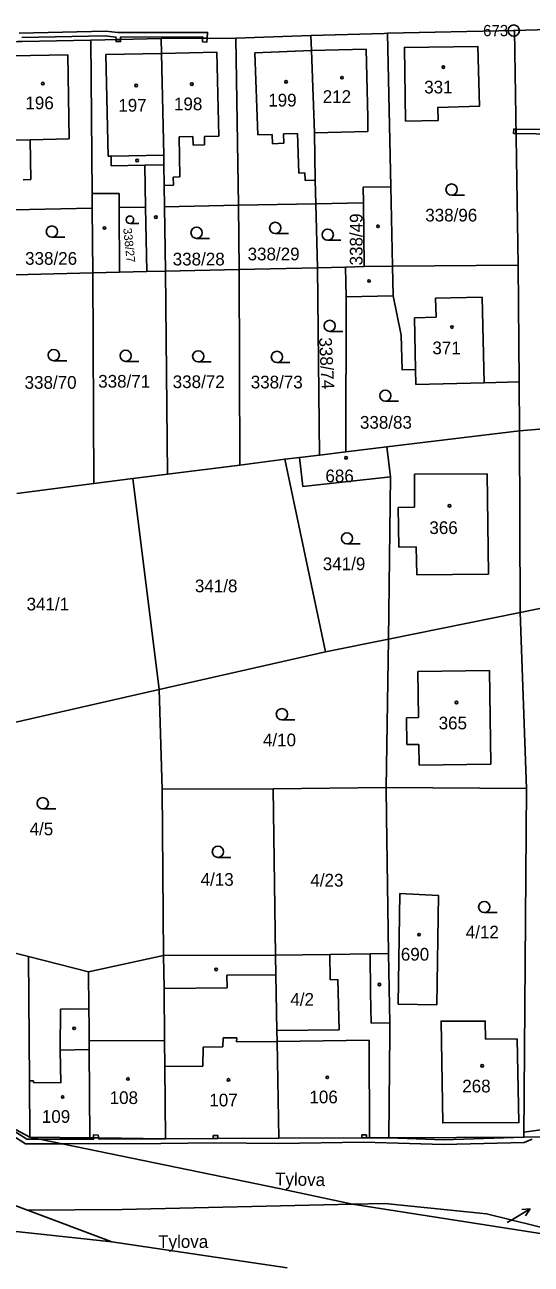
# Model space of a CAD drawing. Extents: x -758582 to -751794, y -998770 to -994350.
# Drawn here: x -755831.8 to -755764, y -995507.3 to -995341.4 of the extents above; entities that cross this region are included whole.
import ezdxf

# ---------------------------------------------------------------- set-up
doc = ezdxf.new("R2010")
doc.units = 0
for name, color, linetype in [('Hranice parcel', 7, 'Continuous'), ('Parcelní čísla', 7, 'Continuous'), ('Pop  PČ popisy', 7, 'Continuous'), ('Vnitřní kresba', 7, 'Continuous'), ('Věcná břemena k části', 7, 'Continuous'), ('Značky bodu BP', 7, 'Continuous'), ('Značky budov', 7, 'Continuous'), ('Značky kultur', 7, 'Continuous')]:
    doc.layers.add(name, color=color, linetype=linetype)

msp = doc.modelspace()

# ---------------------------------------------------------------- linework, layer by layer
at = {"layer": 'Hranice parcel'}
for p, q in [((-755766.27, -995342.19), (-755783.26, -995342.59)), ((-755753.88, -995341.9), (-755766.27, -995342.19)), ((-755765.77, -995373.61), (-755766.27, -995342.19)), ((-755813.51, -995343.29), (-755822.92, -995343.49)), ((-755803.52, -995343.22), (-755813.51, -995343.29)), ((-755793.5, -995342.86), (-755803.52, -995343.22)), ((-755803.19, -995365.6), (-755803.52, -995343.22)), ((-755803.19, -995365.6), (-755792.83, -995365.4)), ((-755792.61, -995373.94), (-755792.83, -995365.4)), ((-755833.22, -995366.18), (-755822.74, -995365.98)), ((-755822.74, -995365.98), (-755822.67, -995374.63)), ((-755813.08, -995365.79), (-755803.19, -995365.6)), ((-755812.97, -995374.41), (-755813.08, -995365.79)), ((-755803.07, -995374.18), (-755803.19, -995365.6)), ((-755786.36, -995373.8), (-755782.59, -995373.72)), ((-755765.77, -995373.61), (-755782.59, -995373.72)), ((-755765.64, -995389.23), (-755765.77, -995373.61)), ((-755833.1, -995374.88), (-755822.67, -995374.63)), ((-755822.67, -995374.63), (-755819.1, -995374.55)), ((-755822.55, -995402.8), (-755822.67, -995374.63)), ((-755819.1, -995374.55), (-755815.43, -995374.47)), ((-755815.43, -995374.47), (-755812.97, -995374.41)), ((-755812.97, -995374.41), (-755803.07, -995374.18)), ((-755812.7, -995401.57), (-755812.97, -995374.41)), ((-755803.07, -995374.18), (-755792.61, -995373.94)), ((-755802.99, -995400.37), (-755803.07, -995374.18)), ((-755792.61, -995373.94), (-755788.87, -995373.86)), ((-755792.34, -995399), (-755792.61, -995373.94)), ((-755786.36, -995373.8), (-755788.87, -995373.86)), ((-755788.87, -995373.86), (-755788.78, -995377.86)), ((-755788.82, -995398.58), (-755788.78, -995377.86)), ((-755765.58, -995395.77), (-755765.64, -995389.23)), ((-755765.58, -995395.77), (-755753.54, -995394.8)), ((-755765.58, -995395.77), (-755783.34, -995397.92)), ((-755765.49, -995420.07), (-755765.58, -995395.77)), ((-755792.34, -995399), (-755788.82, -995398.58)), ((-755788.82, -995398.58), (-755783.34, -995397.92)), ((-755783.34, -995397.92), (-755782.83, -995401.91)), ((-755802.99, -995400.37), (-755796.97, -995399.56)), ((-755796.97, -995399.56), (-755795.01, -995399.32)), ((-755791.55, -995425.33), (-755796.97, -995399.56)), ((-755795.01, -995399.32), (-755792.34, -995399)), ((-755817.31, -995402.15), (-755812.7, -995401.57)), ((-755812.7, -995401.57), (-755802.99, -995400.37)), ((-755782.83, -995401.91), (-755783.13, -995423.63)), ((-755832.84, -995404.14), (-755822.55, -995402.8)), ((-755822.55, -995402.8), (-755817.31, -995402.15)), ((-755813.81, -995430.38), (-755817.31, -995402.15)), ((-755753, -995417.54), (-755765.49, -995420.07)), ((-755765.49, -995420.07), (-755783.13, -995423.63)), ((-755764.66, -995443.61), (-755765.49, -995420.07)), ((-755783.13, -995423.63), (-755791.55, -995425.33)), ((-755783.13, -995423.63), (-755783.4, -995443.47)), ((-755791.55, -995425.33), (-755813.81, -995430.38)), ((-755813.81, -995430.38), (-755838.55, -995435.99)), ((-755813.4, -995443.71), (-755813.81, -995430.38)), ((-755813.4, -995443.71), (-755798.53, -995443.67)), ((-755813.22, -995465.96), (-755813.4, -995443.71)), ((-755798.53, -995443.67), (-755783.4, -995443.47)), ((-755798.21, -995465.91), (-755798.53, -995443.67)), ((-755783.4, -995443.47), (-755764.66, -995443.61)), ((-755764.66, -995443.61), (-755764.98, -995490.26)), ((-755831.29, -995466.07), (-755840.09, -995463.93)), ((-755823.23, -995468.14), (-755831.29, -995466.07)), ((-755813.22, -995465.96), (-755823.23, -995468.14)), ((-755798.21, -995465.91), (-755813.22, -995465.96)), ((-755790.97, -995465.81), (-755798.21, -995465.91)), ((-755840.32, -995485.32), (-755831.1, -995490.25)), ((-755831.1, -995490.25), (-755823.09, -995490.34)), ((-755783.06, -995490.34), (-755764.98, -995490.26)), ((-755764.98, -995490.26), (-755751.84, -995489.99)), ((-755787.94, -995499.24), (-755783.62, -995499.14)), ((-755787.94, -995499.24), (-755753.53, -995504.57)), ((-755783.62, -995499.14), (-755769.99, -995500.51)), ((-755820.13, -995504.28), (-755831.43, -995500.02)), ((-755769.99, -995500.51), (-755753.53, -995504.57)), ((-755796.67, -995507.74), (-755820.13, -995504.28))]:
    msp.add_line(p, q, dxfattribs=at)
for points in [[(-755822.92, -995343.49), (-755832.14, -995343.69), (-755832.74, -995343.7), (-755833.54, -995343.72)], [(-755822.74, -995365.98), (-755822.76, -995364.02), (-755822.92, -995343.49)], [(-755813.08, -995365.79), (-755813.11, -995362.95), (-755813.16, -995360.19), (-755813.19, -995358.89), (-755813.47, -995345.29), (-755813.51, -995343.29)], [(-755783.26, -995342.59), (-755783.7, -995342.63), (-755793.5, -995342.86)], [(-755792.83, -995365.4), (-755792.9, -995362.24), (-755793.03, -995355.91), (-755793.43, -995344.9), (-755793.5, -995342.86)], [(-755782.59, -995373.72), (-755782.77, -995365.18), (-755782.81, -995363.13), (-755783.26, -995342.59)], [(-755780.84, -995354.32), (-755776.47, -995354.26), (-755776.52, -995352.5), (-755770.92, -995352.33), (-755771.16, -995344.33), (-755780.99, -995344.47), (-755780.84, -995354.32)], [(-755792.83, -995365.4), (-755786.47, -995365.26), (-755786.36, -995373.8)], [(-755819.1, -995374.55), (-755819.14, -995365.91), (-755815.61, -995365.84), (-755815.43, -995374.47)], [(-755788.78, -995377.86), (-755782.5, -995377.72), (-755781.4, -995382.99), (-755781.29, -995387.59), (-755779.49, -995387.55), (-755779.45, -995389.55), (-755770.32, -995389.34), (-755765.64, -995389.23)], [(-755782.83, -995401.91), (-755794.56, -995403.23), (-755795.01, -995399.32)], [(-755783.4, -995443.47), (-755783.37, -995447.37), (-755783.09, -995465.69)], [(-755781.83, -995472.46), (-755781.59, -995457.66), (-755776.41, -995457.93), (-755776.65, -995472.54), (-755781.83, -995472.46)], [(-755831.29, -995466.07), (-755831.16, -995482.73), (-755831.1, -995490.25)], [(-755813.22, -995465.96), (-755813.12, -995470.35), (-755813.07, -995477.31), (-755813.02, -995480.79), (-755812.97, -995490.5)], [(-755798.04, -995475.98), (-755798.17, -995468.52), (-755798.21, -995465.91)], [(-755790.97, -995465.81), (-755790.91, -995469.19), (-755789.89, -995469.16), (-755789.73, -995475.88), (-755798.04, -995475.98)], [(-755783.09, -995465.69), (-755785.58, -995465.73), (-755790.97, -995465.81)], [(-755783.06, -995490.34), (-755782.93, -995476.29), (-755782.95, -995474.96), (-755783.09, -995465.69)], [(-755823.23, -995468.14), (-755823.19, -995473.14), (-755823.18, -995475.27), (-755823.17, -995477.38), (-755823.16, -995478.54), (-755823.09, -995490.34)], [(-755831.43, -995500.02), (-755834.39, -995498.91), (-755843.49, -995495.24), (-755854.92, -995487.79), (-755869.22, -995474.51)], [(-755765.89, -995477.1), (-755770.13, -995477.13), (-755770.16, -995474.73), (-755776.08, -995474.73), (-755775.85, -995488.36), (-755765.66, -995488.3), (-755765.89, -995477.1)], [(-755798.04, -995475.98), (-755798.01, -995477.44), (-755797.79, -995490.38)], [(-755831.1, -995490.25), (-755797.72, -995497.11), (-755787.94, -995499.24)], [(-755823.09, -995490.34), (-755822.57, -995490.35), (-755821.87, -995490.36), (-755812.97, -995490.5)], [(-755812.97, -995490.5), (-755806.55, -995490.45), (-755805.95, -995490.44), (-755797.79, -995490.38)], [(-755797.79, -995490.38), (-755785.65, -995490.33), (-755783.06, -995490.34)], [(-755831.43, -995500.02), (-755818.76, -995499.95), (-755787.94, -995499.24)], [(-755862.96, -995509.12), (-755847.86, -995501.28), (-755820.13, -995504.28)]]:
    msp.add_lwpolyline(points, dxfattribs=at)
at = {"layer": 'Pop  PČ popisy'}
for p, q in [((-755767.21, -995501.68), (-755766.74, -995501.4)), ((-755766.74, -995501.4), (-755764.17, -995499.85)), ((-755764.17, -995499.85), (-755765.28, -995499.94)), ((-755764.17, -995499.85), (-755764.77, -995500.8))]:
    msp.add_line(p, q, dxfattribs=at)
at = {"layer": 'Vnitřní kresba'}
for p, q in [((-755826.03, -995345.47), (-755833.49, -995345.61)), ((-755825.82, -995356.72), (-755826.03, -995345.47)), ((-755820.92, -995345.44), (-755813.47, -995345.29)), ((-755820.64, -995359.04), (-755820.92, -995345.44)), ((-755806.07, -995345.13), (-755813.47, -995345.29)), ((-755805.83, -995356.33), (-755806.07, -995345.13)), ((-755793.43, -995344.9), (-755800.99, -995345.18)), ((-755800.99, -995345.18), (-755800.59, -995356.18)), ((-755793.43, -995344.9), (-755786.08, -995344.73)), ((-755786.08, -995344.73), (-755785.89, -995353.84)), ((-755785.89, -995353.84), (-755785.86, -995355.73)), ((-755833.35, -995356.89), (-755831.07, -995356.84)), ((-755831.07, -995356.84), (-755825.82, -995356.72)), ((-755830.96, -995362.15), (-755831.07, -995356.84)), ((-755811.13, -995356.44), (-755809.28, -995356.4)), ((-755811.02, -995361.79), (-755811.13, -995356.44)), ((-755809.28, -995356.4), (-755809.26, -995357.55)), ((-755807.73, -995356.37), (-755805.83, -995356.33)), ((-755807.71, -995357.52), (-755807.73, -995356.37)), ((-755798.69, -995356.11), (-755800.59, -995356.18)), ((-755798.65, -995357.36), (-755798.69, -995356.11)), ((-755795.29, -995355.99), (-755797.14, -995356.05)), ((-755797.14, -995356.05), (-755797.1, -995357.3)), ((-755795.1, -995361.28), (-755795.29, -995355.99)), ((-755785.86, -995355.73), (-755793.03, -995355.91)), ((-755809.26, -995357.55), (-755807.71, -995357.52)), ((-755797.1, -995357.3), (-755798.65, -995357.36)), ((-755820.24, -995359.03), (-755820.64, -995359.04)), ((-755813.19, -995358.89), (-755820.24, -995359.03)), ((-755820.22, -995360.33), (-755820.24, -995359.03)), ((-755815.72, -995360.24), (-755820.22, -995360.33)), ((-755813.16, -995360.19), (-755815.72, -995360.24)), ((-755815.61, -995365.84), (-755815.72, -995360.24)), ((-755831.98, -995362.17), (-755830.96, -995362.15)), ((-755811.9, -995361.81), (-755811.02, -995361.79)), ((-755811.87, -995362.92), (-755811.9, -995361.81)), ((-755794.32, -995361.26), (-755795.1, -995361.28)), ((-755794.28, -995362.29), (-755794.32, -995361.26)), ((-755813.11, -995362.95), (-755811.87, -995362.92)), ((-755792.9, -995362.24), (-755794.28, -995362.29)), ((-755786.5, -995363.18), (-755782.81, -995363.13)), ((-755786.47, -995365.26), (-755786.5, -995363.18)), ((-755822.76, -995364.02), (-755819.15, -995364)), ((-755819.15, -995364), (-755819.14, -995365.91)), ((-755782.5, -995377.72), (-755782.59, -995373.72)), ((-755776.81, -995378.01), (-755770.58, -995377.87)), ((-755776.81, -995378.01), (-755776.75, -995380.58)), ((-755770.58, -995377.87), (-755770.32, -995389.34)), ((-755776.75, -995380.58), (-755779.65, -995380.65)), ((-755779.65, -995380.65), (-755779.49, -995387.55)), ((-755769.92, -995401.53), (-755779.65, -995401.57)), ((-755779.63, -995406), (-755779.65, -995401.57)), ((-755769.92, -995401.53), (-755769.74, -995414.92)), ((-755779.63, -995406), (-755781.8, -995406.03)), ((-755781.8, -995406.03), (-755781.73, -995411.33)), ((-755781.73, -995411.33), (-755779.39, -995411.3)), ((-755779.39, -995411.3), (-755779.34, -995415.05)), ((-755779.34, -995415.05), (-755769.74, -995414.92)), ((-755779.17, -995427.97), (-755769.58, -995427.84)), ((-755779.1, -995434.12), (-755779.17, -995427.97)), ((-755769.58, -995427.84), (-755769.41, -995440.38)), ((-755779.1, -995434.12), (-755780.71, -995434.15)), ((-755780.71, -995434.15), (-755780.66, -995437.73)), ((-755780.66, -995437.73), (-755779.04, -995437.71)), ((-755779.04, -995437.71), (-755779, -995440.51)), ((-755779, -995440.51), (-755769.41, -995440.38)), ((-755785.5, -995470.91), (-755785.58, -995465.73)), ((-755798.17, -995468.52), (-755804.75, -995468.57)), ((-755804.75, -995468.57), (-755804.7, -995470.26)), ((-755804.7, -995470.26), (-755813.12, -995470.35)), ((-755785.44, -995474.99), (-755785.5, -995470.91)), ((-755827.02, -995478.6), (-755827, -995473.14)), ((-755827, -995473.14), (-755825.81, -995473.09)), ((-755825.81, -995473.09), (-755823.19, -995473.14)), ((-755782.95, -995474.96), (-755785.44, -995474.99)), ((-755823.17, -995477.38), (-755813.07, -995477.31)), ((-755807.91, -995478.2), (-755807.97, -995480.75)), ((-755805.28, -995478.19), (-755807.91, -995478.2)), ((-755805.25, -995476.99), (-755805.28, -995478.19)), ((-755803.41, -995476.97), (-755805.25, -995476.99)), ((-755803.46, -995477.5), (-755803.41, -995476.97)), ((-755798.01, -995477.44), (-755803.46, -995477.5)), ((-755785.7, -995477.3), (-755798.01, -995477.44)), ((-755785.7, -995477.3), (-755785.65, -995490.33)), ((-755827.02, -995478.6), (-755823.16, -995478.54)), ((-755826.96, -995482.98), (-755827.02, -995478.6)), ((-755807.97, -995480.75), (-755813.02, -995480.79)), ((-755831.16, -995482.73), (-755830.6, -995482.74)), ((-755830.6, -995482.74), (-755830.61, -995482.93)), ((-755830.61, -995482.93), (-755826.96, -995482.98))]:
    msp.add_line(p, q, dxfattribs=at)
at = {"layer": 'Věcná břemena k části'}
for points in [[(-755832.19, -995343.16), (-755821, -995342.92), (-755819.58, -995343.1), (-755819.57, -995343.42), (-755818.97, -995343.41), (-755818.98, -995343.1), (-755807.96, -995343.06), (-755807.98, -995343.25), (-755807.37, -995343.25), (-755807.32, -995342.46), (-755819.32, -995342.5), (-755820.95, -995342.32), (-755832.52, -995342.56)], [(-755755.18, -995355.56), (-755766.06, -995355.39), (-755766.05, -995355.99), (-755755.14, -995356.16)], [(-755762.05, -995489.2), (-755764.98, -995489.61), (-755764.98, -995490.26), (-755775.75, -995490.63), (-755783.06, -995490.34), (-755785.65, -995490.33), (-755786.06, -995490.33), (-755786.66, -995490.33), (-755797.79, -995490.38), (-755805.95, -995490.44), (-755806.55, -995490.45), (-755812.97, -995490.5), (-755821.83, -995490.53), (-755821.87, -995490.36), (-755822.57, -995490.35), (-755822.58, -995490.53), (-755829.69, -995490.54), (-755831.51, -995490.54), (-755836.74, -995487.23)], [(-755835.19, -995488.93), (-755831.69, -995491.14), (-755826.78, -995491.14), (-755813.59, -995491.11), (-755806.35, -995491.01), (-755797.89, -995491.09), (-755786.39, -995490.93), (-755780.31, -995491.09), (-755775.76, -995491.23), (-755764.96, -995490.99), (-755763.87, -995490.51)]]:
    msp.add_lwpolyline(points, dxfattribs=at)
for points in [[(-755819.57, -995343.42), (-755819.55, -995343.7), (-755818.95, -995343.69), (-755818.97, -995343.41)], [(-755808.01, -995343.75), (-755807.41, -995343.76), (-755807.37, -995343.25), (-755807.98, -995343.25)], [(-755766.36, -995355.38), (-755766.37, -995355.98), (-755766.05, -995355.99), (-755766.06, -995355.39)], [(-755822.57, -995490.35), (-755821.87, -995490.36), (-755821.96, -995489.97), (-755822.56, -995489.94)], [(-755806.55, -995490.04), (-755806.55, -995490.45), (-755805.95, -995490.44), (-755805.95, -995490.03)], [(-755786.66, -995489.96), (-755786.66, -995490.33), (-755786.06, -995490.33), (-755786.06, -995489.96)]]:
    msp.add_lwpolyline(points, close=True, dxfattribs=at)
at = {"layer": 'Značky bodu BP'}
for radius in [0.75, 0.03]:
    msp.add_circle((-755766.35, -995342.22), radius, dxfattribs=at)
at = {"layer": 'Značky budov'}
for centre in [(-755775.77, -995347.12), (-755796.82, -995349.07), (-755789.34, -995348.52), (-755829.37, -995349.32), (-755816.87, -995349.57), (-755809.43, -995349.38), (-755816.75, -995359.61), (-755814.23, -995367.18), (-755821.1, -995368.63), (-755784.51, -995368.4), (-755785.71, -995375.72), (-755774.62, -995381.88), (-755788.79, -995399.39), (-755774.94, -995405.8), (-755774.02, -995432.12), (-755779.02, -995463.17), (-755806.17, -995467.81), (-755784.33, -995469.83), (-755825.17, -995475.7), (-755770.57, -995480.72), (-755817.97, -995482.47), (-755804.51, -995482.6), (-755791.3, -995482.25), (-755826.71, -995484.88)]:
    msp.add_circle(centre, 0.175, dxfattribs=at)
at = {"layer": 'Značky kultur'}
for p, q in [((-755774.67, -995364.24), (-755772.92, -995364.24)), ((-755817.7, -995368.03), (-755816.53, -995368.03)), ((-755828.15, -995369.86), (-755826.4, -995369.86)), ((-755808.79, -995370.02), (-755807.04, -995370.02)), ((-755798.26, -995369.37), (-755796.51, -995369.37)), ((-755791.24, -995370.28), (-755789.49, -995370.28)), ((-755790.98, -995382.47), (-755789.23, -995382.47)), ((-755827.9, -995386.39), (-755826.15, -995386.39)), ((-755818.28, -995386.48), (-755816.53, -995386.48)), ((-755808.57, -995386.55), (-755806.82, -995386.55)), ((-755798.04, -995386.63), (-755796.29, -995386.63)), ((-755783.53, -995391.81), (-755781.78, -995391.81)), ((-755788.66, -995410.9), (-755786.91, -995410.9)), ((-755797.38, -995434.42), (-755795.63, -995434.42)), ((-755829.37, -995446.33), (-755827.62, -995446.33)), ((-755805.94, -995452.83), (-755804.19, -995452.83)), ((-755770.3, -995460.22), (-755768.55, -995460.22))]:
    msp.add_line(p, q, dxfattribs=at)
for centre, radius in [((-755774.67, -995363.49), 0.75), ((-755817.71, -995367.53), 0.502), ((-755828.15, -995369.11), 0.75), ((-755808.79, -995369.27), 0.75), ((-755798.26, -995368.62), 0.75), ((-755791.24, -995369.53), 0.75), ((-755790.98, -995381.72), 0.75), ((-755827.9, -995385.64), 0.75), ((-755818.28, -995385.73), 0.75), ((-755808.57, -995385.8), 0.75), ((-755798.04, -995385.88), 0.75), ((-755783.53, -995391.06), 0.75), ((-755788.66, -995410.15), 0.75), ((-755797.38, -995433.67), 0.75), ((-755829.37, -995445.58), 0.75), ((-755805.94, -995452.08), 0.75), ((-755770.3, -995459.47), 0.75)]:
    msp.add_circle(centre, radius, dxfattribs=at)

# ---------------------------------------------------------------- texts
at = {"layer": 'Parcelní čísla'}
for s, p in [('212', (-755791.91, -995351.9)), ('331', (-755778.33, -995350.63)), ('196', (-755831.69, -995352.75)), ('197', (-755819.26, -995353.07)), ('198', (-755811.81, -995352.88)), ('199', (-755799.2, -995352.38)), ('338/96', (-755778.19, -995367.76)), ('338/26', (-755831.73, -995373.55)), ('338/28', (-755811.98, -995373.64)), ('338/29', (-755801.96, -995372.96)), ('371', (-755777.24, -995385.52)), ('338/70', (-755831.8, -995390.14)), ('338/71', (-755821.95, -995389.99)), ('338/72', (-755811.98, -995390.05)), ('338/73', (-755801.54, -995390.09)), ('338/83', (-755786.93, -995395.48)), ('686', (-755791.55, -995402.65)), ('366', (-755777.64, -995409.57)), ('341/9', (-755791.9, -995414.41)), ('341/8', (-755809.01, -995417.36)), ('341/1', (-755831.53, -995419.79)), ('365', (-755776.4, -995435.7)), ('4/10', (-755799.91, -995437.97)), ('4/5', (-755831.13, -995449.87)), ('4/13', (-755808.25, -995456.63)), ('4/23', (-755793.56, -995456.73)), ('4/12', (-755772.77, -995463.67)), ('690', (-755781.46, -995466.64)), ('4/2', (-755796.24, -995472.67)), ('268', (-755773.24, -995484.27)), ('108', (-755820.42, -995485.82)), ('107', (-755807.08, -995486.14)), ('106', (-755793.69, -995485.73)), ('109', (-755829.49, -995488.34))]:
    msp.add_text(s, height=1.7, dxfattribs=at).set_placement(p)
for s, height, rotation, p in [('338/49', 1.7, 90, (-755786.58, -995373.64)), ('338/27', 1.14, 276, (-755818.61, -995368.68)), ('338/74', 1.7, 273, (-755792.41, -995383.31))]:
    msp.add_text(s, height=height, rotation=rotation, dxfattribs=at).set_placement(p)
at = {"layer": 'Pop  PČ popisy'}
msp.add_text('Tylova', height=1.7, rotation=359, dxfattribs=at).set_placement((-755798.3, -995496.69))
msp.add_text('Tylova', height=1.7, dxfattribs=at).set_placement((-755813.93, -995505.07))
at = {"layer": 'Značky bodu BP'}
msp.add_text('673', height=1.5, dxfattribs=at).set_placement((-755770.45, -995342.97))

doc.saveas('drawing.dxf')
